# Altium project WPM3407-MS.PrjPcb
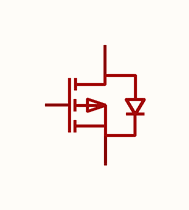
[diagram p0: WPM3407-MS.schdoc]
1 sheet, 1 parts. Net scope: global (net labels, ports and power ports of the same name join across sheets).

## Sheet WPM3407-MS.schdoc
size 127 x 101 mm

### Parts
Q?  wpm3407-ms  [SOT-23-3_L2.9-W1.6-P1.90-LS2.8-BR]  (value not drawn)

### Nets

Not connected (* = marked no-connect by the designer): Q? 1(G) 2(S) 3(D)

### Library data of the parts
Q? = wpm3407-ms: 数量:1个P沟道;漏源电压(Vdss):30V;连续漏极电流(Id):4.1A;导通电阻(RDS(on)):48mΩ@10V;耗散功率(Pd):1.4W;阈值电压(Vgs(th)):1.5V;; Manufacturer: MSKSEMI(美森科); AddInBom: yes; ModelId: 89cb27a44ab2466697082bb9fd73a7d0; ModelName: SOT-23-3L_L2.9-W1.6-H1.1-LS2.8-P0.95; ModelTransform: 114.173,110.236,0,90,0,0,0,0,0; Number: 1个P沟道; Drain to Source Voltage: 30V; Current - Continuous Drain(Id): 4.1A; Pd - Power Dissipation: 1.4W; Gate Threshold Voltage (Vgs(th)): 1.5V; Gate Charge(Qg): 12.5nC@10V; Input Capacitance(Ciss): 650pF; Reverse Transfer Capacitance (Crss@Vds): 65pF; Type: P沟道; Output Capacitance(Coss): 105pF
